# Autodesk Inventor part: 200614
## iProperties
Created: 2007-11
Part Number: 200614
Document SubType Name: Modeling
Designer: JJ
Density: 7.85 g/cm^3
Mass: 7.66718 g
Surface Area: 6.36635 cm^2
Volume: 0.976711 cm^3
Material: Steel
Description: MOTOR CONNECTING ROD
Component Category: Lower Component
Author: JJ
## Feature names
1. Extrusion1
2. Extrusion2
3. Fillet1
4. Revolution1
5. Mirror1
6. Chamfer2
7. Split2
